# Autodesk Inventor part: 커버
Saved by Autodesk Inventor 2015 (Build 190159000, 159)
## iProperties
Created: 2024-11
Part Number: 커버
Material: 일반
Document SubType Name: Modeling
Designer: 102-5
Density: 1 g/cm^3
Appearance: 기본값
Author: 102-5
Author: jhkim
Creation Date: 2024-10-25
Sending System: Autodesk Inventor 2025
Preprocessor: ST-DEVELOPER v20
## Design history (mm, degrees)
node "커버1"
node "솔리드1"
node "기준1"
